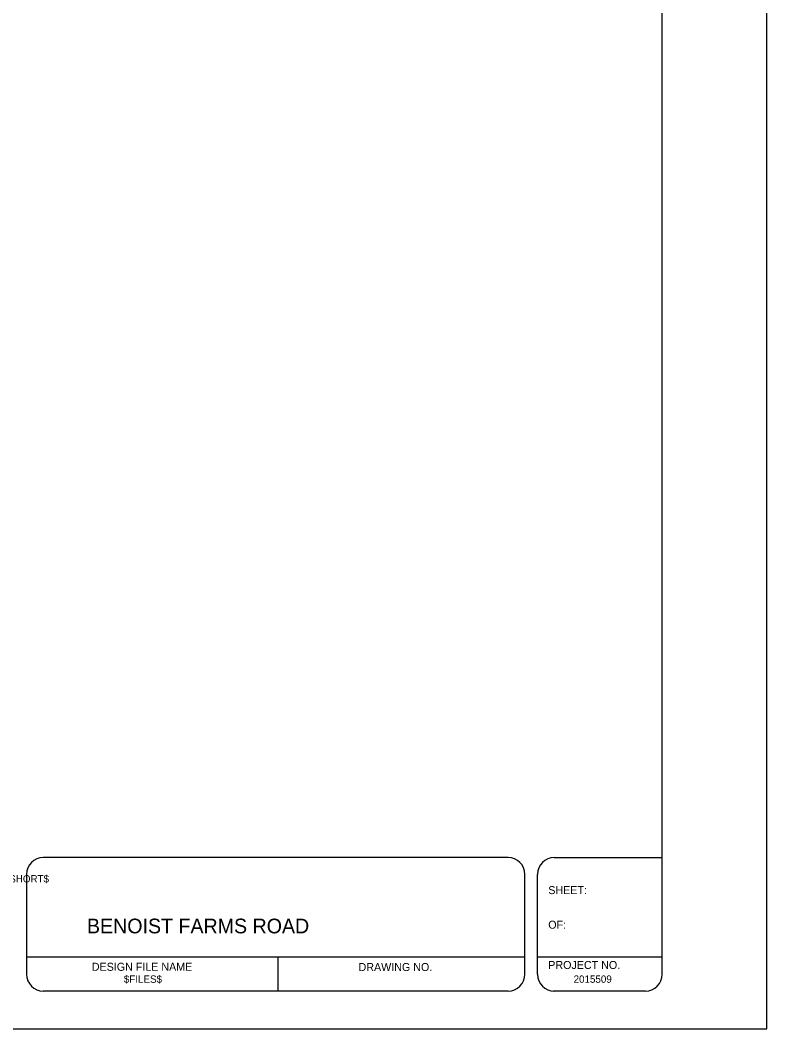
# Model space of a CAD drawing. Extents: x 783907 to 784590, y 832093 to 832609.
# Drawn here: x 784349.7 to 784388.9, y 832093.3 to 832146.3 of the extents above; entities that cross this region are included whole.
import ezdxf

# ---------------------------------------------------------------- set-up
doc = ezdxf.new("R2010")
doc.units = 0
for name, color, linetype in [('Default', 7, 'Continuous'), ('PlotBorder_dp', 7, 'Continuous'), ('TextMinor', 7, 'Continuous')]:
    doc.layers.add(name, color=color, linetype=linetype)

msp = doc.modelspace()

# ---------------------------------------------------------------- linework, layer by layer
at = {"layer": 'Default'}
for p, q in [((784383.44, 832096.122), (784383.44, 832197.32)), ((784375.338, 832102.255), (784350.9, 832102.255)), ((784377.764, 832102.255), (784383.44, 832102.255)), ((784350.017, 832101.373), (784350.017, 832096.123)), ((784376.22, 832096.12), (784376.22, 832101.371)), ((784376.882, 832096.12), (784376.882, 832101.371)), ((784376.209, 832097.014), (784350.008, 832097.014)), ((784363.241, 832095.25), (784363.241, 832097.014)), ((784383.44, 832097.014), (784376.915, 832097.014)), ((784375.338, 832095.241), (784350.9, 832095.241)), ((784382.558, 832095.239), (784377.71, 832095.239))]:
    msp.add_line(p, q, dxfattribs=at)
for centre, major_axis, start_param, end_param in [((784350.9, 832101.373), (0, 0.882), 0, 1.570796), ((784375.338, 832101.371), (0, 0.882), 4.712389, 6.283185), ((784377.764, 832101.371), (0, -0.882), 3.141593, 4.712389), ((784350.9, 832096.123), (0, -0.882), 4.712389, 6.283185), ((784375.338, 832096.123), (0, 0.882), 3.141593, 4.712389), ((784377.764, 832096.12), (0, -0.882), 4.712389, 6.283185), ((784382.558, 832096.122), (0, -0.882), 0, 1.570796)]:
    msp.add_ellipse(centre, major_axis=major_axis, ratio=0.999927, start_param=start_param, end_param=end_param, dxfattribs=at)
at = {"layer": 'PlotBorder_dp'}
msp.add_lwpolyline([(784223.94, 832093.255), (784388.94, 832093.255), (784388.94, 832199.255), (784223.94, 832199.255)], close=True, dxfattribs=at)

# ---------------------------------------------------------------- texts
at = {"layer": 'Default'}
for s, height, p in [('SHEET:', 0.4207, (784377.448, 832100.333)), ('   BENOIST FARMS ROAD   ', 0.77091, (784352.335, 832098.273)), ('OF:', 0.4207, (784377.448, 832098.515)), ('PROJECT NO.', 0.42066, (784377.448, 832096.399)), ('DESIGN FILE NAME', 0.42066, (784353.449, 832096.304)), ('DRAWING NO.', 0.42066, (784367.475, 832096.291)), ('$FILES$', 0.3855, (784355.134, 832095.674)), ('2015509', 0.3855, (784378.78, 832095.674))]:
    msp.add_text(s, height=height, dxfattribs=at).set_placement(p)
at = {"layer": 'TextMinor'}
msp.add_text('$SCALESHORT$', height=0.38546, dxfattribs=at).set_placement((784347.131, 832100.944))

doc.saveas('drawing.dxf')
